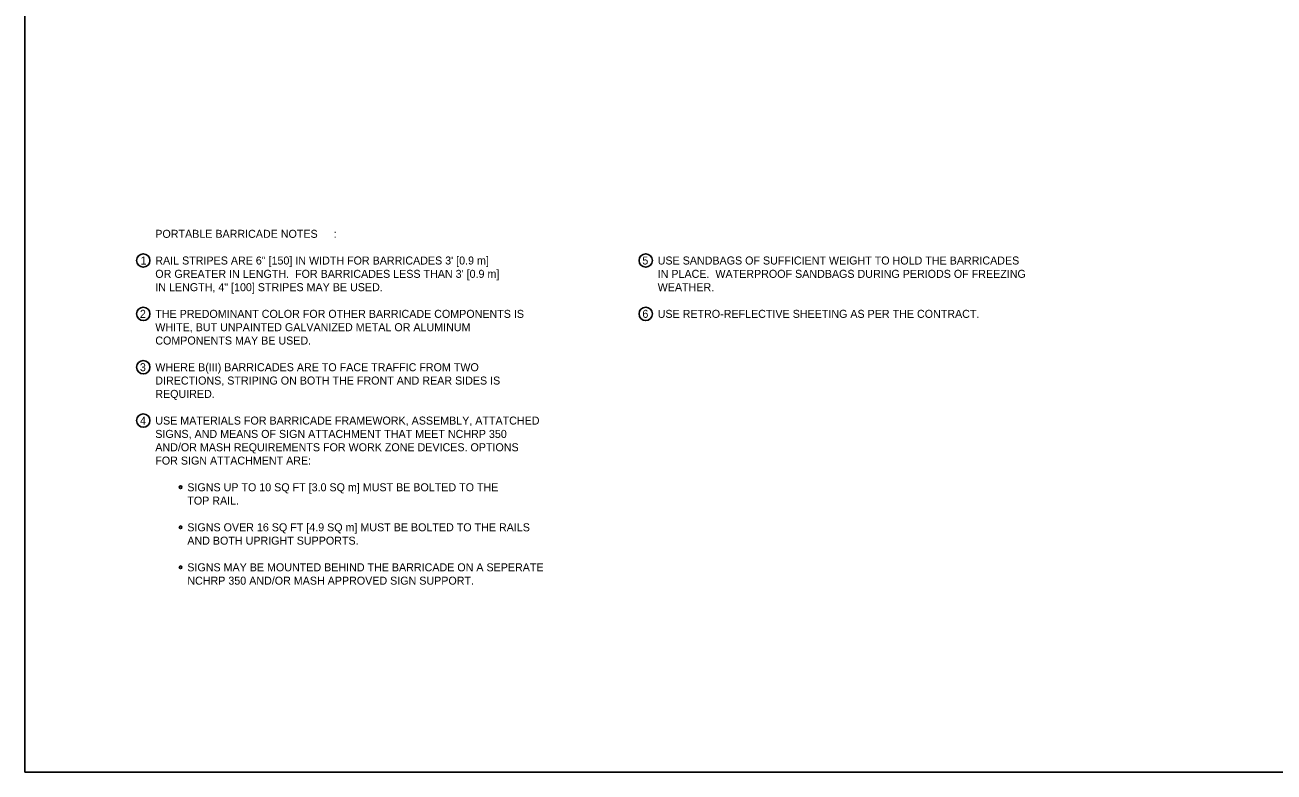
# Model space of a CAD drawing. Extents: x 49991.4 to 50021, y 49987.6 to 50011.4.
# Drawn here: x 49999.38 to 50008.75, y 49987.8 to 49993.4 of the extents above; entities that cross this region are included whole.
import ezdxf

# ---------------------------------------------------------------- set-up
doc = ezdxf.new("R2010")
doc.units = 0
doc.layers.add('Level 1', color=7, linetype='Continuous')
doc.layers.add('Level 2', color=7, linetype='Continuous')

msp = doc.modelspace()

# ---------------------------------------------------------------- linework, layer by layer
at = {"layer": 'Level 1'}
msp.add_lwpolyline([(49999.3835, 49998.9992), (50016.7501, 49998.9992), (50016.7501, 49987.7988), (49999.3835, 49987.7988)], close=True, dxfattribs=at)
at = {"layer": 'Level 2'}
for centre, radius in [((50000.2704, 49991.6334), 0.05), ((50004.0362, 49991.6334), 0.05), ((50000.2704, 49991.2334), 0.05), ((50004.0362, 49991.2334), 0.05), ((50000.2704, 49990.8334), 0.05), ((50000.2704, 49990.4334), 0.05), ((50000.5502, 49989.9334), 0.0101), ((50000.5502, 49989.6334), 0.0101), ((50000.5502, 49989.3334), 0.0101)]:
    msp.add_circle(centre, radius, dxfattribs=at)

# ---------------------------------------------------------------- texts
for s, p in [('PORTABLE BARRICADE NOTES', (50000.3604, 49991.8034)), (':', (50001.697, 49991.8034)), ('1', (50000.2506, 49991.6034)), ('RAIL STRIPES ARE 6" [150] IN WIDTH FOR BARRICADES 3\' [0.9 m]', (50000.3604, 49991.6034)), ('5', (50004.0113, 49991.6034)), ('USE SANDBAGS OF SUFFICIENT WEIGHT TO HOLD THE BARRICADES', (50004.1262, 49991.6034)), ("OR GREATER IN LENGTH.  FOR BARRICADES LESS THAN 3' [0.9 m]", (50000.3604, 49991.5034)), ('IN PLACE.  WATERPROOF SANDBAGS DURING PERIODS OF FREEZING', (50004.1262, 49991.5034)), ('IN LENGTH, 4" [100] STRIPES MAY BE USED.', (50000.3604, 49991.4034)), ('WEATHER.', (50004.1262, 49991.4034)), ('2', (50000.2452, 49991.2034)), ('THE PREDOMINANT COLOR FOR OTHER BARRICADE COMPONENTS IS', (50000.3604, 49991.2034)), ('6', (50004.0116, 49991.2034)), ('USE RETRO-REFLECTIVE SHEETING AS PER THE CONTRACT. ', (50004.1262, 49991.2034)), ('WHITE, BUT UNPAINTED GALVANIZED METAL OR ALUMINUM', (50000.3604, 49991.1034)), ('COMPONENTS MAY BE USED.', (50000.3604, 49991.0034)), ('3', (50000.2452, 49990.8034)), ('WHERE B(III) BARRICADES ARE TO FACE TRAFFIC FROM TWO', (50000.3604, 49990.8034)), ('DIRECTIONS, STRIPING ON BOTH THE FRONT AND REAR SIDES IS', (50000.3604, 49990.7034)), ('REQUIRED.', (50000.3604, 49990.6034)), ('4', (50000.2464, 49990.4034)), ('USE MATERIALS FOR BARRICADE FRAMEWORK, ASSEMBLY, ATTATCHED', (50000.3604, 49990.4034)), ('SIGNS, AND MEANS OF SIGN ATTACHMENT THAT MEET NCHRP 350', (50000.3604, 49990.3034)), ('AND/OR MASH REQUIREMENTS FOR WORK ZONE DEVICES. OPTIONS', (50000.3604, 49990.2034)), ('FOR SIGN ATTACHMENT ARE:', (50000.3604, 49990.1034)), ('SIGNS UP TO 10 SQ FT [3.0 SQ m] MUST BE BOLTED TO THE', (50000.6004, 49989.9034)), ('TOP RAIL.', (50000.6004, 49989.8034)), ('SIGNS OVER 16 SQ FT [4.9 SQ m] MUST BE BOLTED TO THE RAILS', (50000.6004, 49989.6034)), ('AND BOTH UPRIGHT SUPPORTS.', (50000.6004, 49989.5034)), ('SIGNS MAY BE MOUNTED BEHIND THE BARRICADE ON A SEPERATE', (50000.6004, 49989.3034)), ('NCHRP 350 AND/OR MASH APPROVED SIGN SUPPORT.', (50000.6004, 49989.2034))]:
    msp.add_text(s, height=0.06, dxfattribs=at).set_placement(p)

doc.saveas('drawing.dxf')
